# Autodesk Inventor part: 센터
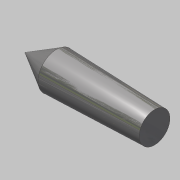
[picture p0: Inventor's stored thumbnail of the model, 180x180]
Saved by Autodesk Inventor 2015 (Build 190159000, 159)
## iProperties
Created: 2019-10
Part Number: 센터
Material: 스테인리스강
Document SubType Name: Modeling
Designer: mduedu
Density: 1 g/cm^3
Appearance: 반광택
Author: mduedu
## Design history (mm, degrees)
sketch "스케치1"
  geometry: L1 (0, 0)-(-31.5, 0); L2 (-31.5, 0)-(-31.5, -0.125); L3 (-31.5, -0.125)-(-23.922, -4.5); L4 (-23.922, -4.5)-(0, -3.751); L5 (0, -3.751)-(0, 0)
  constraints: 10 end point, 1 horizontal, 1 parallel, 1 perpendicular
  dimensions: "d0" = 31.5 distance of L1.start L1.end; "d1" = 7.502 diameter of L4.end L1; "d2" = 30 deg angle of L1 L3; "d3" = 7.578 horizontal distance of L2.end L3.end; "d5" = 0.25 diameter of L2.end L1; "d6" = 23.922 horizontal distance of L3.end L4.end (derived); "d7" = 9.00032 diameter of L3.end L1 (derived)
revolve "회전1" sketch "스케치1" stored, may be unused: angle "d8" = 90 deg
node "솔리드1"
